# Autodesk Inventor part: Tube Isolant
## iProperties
Shininess: 64.0
Length Units: 11269
Angle Units: 11279
Time Units: 11290
Mass Units: 11283
Length Display Precision: 3
Angle Display Precision: 2
Compacted: True
Part Number: Tube Isolant
Document SubType Name: Modeling
Created: 2005-01
Material: Par défaut
Designer: lolo (Laurent Moretti)
Density: 0.0
Volumn: 0.0
Area: 0.0
PropertySet Name: Model Information
Control State: 0
Master: False
Checked Out: False
Author: lolo (Laurent Moretti)
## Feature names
1. Extrusion1
